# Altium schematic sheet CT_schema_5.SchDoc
size 283 x 147 mm
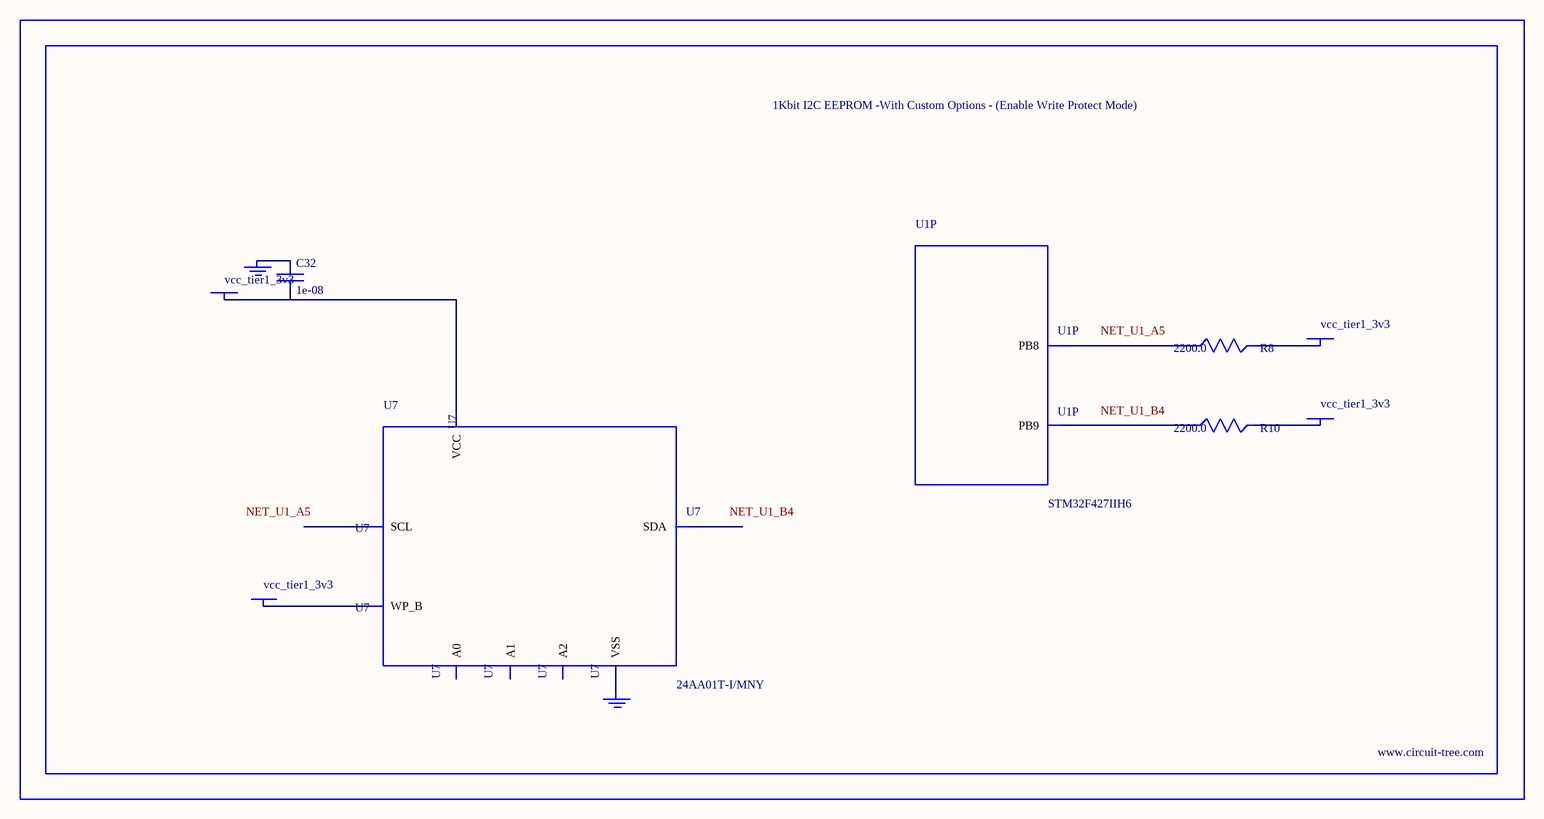
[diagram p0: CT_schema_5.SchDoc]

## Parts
BORDER4  (no value)
C32  1e-08  [C0402]
GND_INSTANCE_4_0  (no value)
GND_INSTANCE_4_1  (no value)
POWER_INSTANCE_4_0  vcc_tier1_3v3
POWER_INSTANCE_4_1  vcc_tier1_3v3
POWER_INSTANCE_4_2  vcc_tier1_3v3
POWER_INSTANCE_4_3  vcc_tier1_3v3
R8  2200.0  [R0603]
R10  2200.0  [R0603]
U1  STM32F427IIH6  [UFBGA176_25]  (part P of 17)
U7  24AA01T-I/MNY  [TDFN-8/6MM]

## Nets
NetC32_1: C32.1 GND_INSTANCE_4_0.0(GND)
NetC32_2: C32.2 POWER_INSTANCE_4_1.0(PWR) U7.8(VCC)
NetGND_INSTANCE_4_1_0: GND_INSTANCE_4_1.0(GND) U7.4(VSS)
NetPOWER_INSTANCE_4_0_0: POWER_INSTANCE_4_0.0(PWR) U7.7(WP_B)
NetPOWER_INSTANCE_4_2_0: POWER_INSTANCE_4_2.0(PWR) R8.2
NetPOWER_INSTANCE_4_3_0: POWER_INSTANCE_4_3.0(PWR) R10.2
NetR8_1: R8.1 U1.A5(PB8)
NetR10_1: R10.1 U1.B4(PB9)

Not connected (* = marked no-connect by the designer): U7 1(A0) 2(A1) 3(A2) 5(SDA) 6(SCL)

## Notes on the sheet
- Labels drawn without touching a wire or pin: NET_U1_A5, NET_U1_B4

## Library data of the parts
BORDER4 = BORDER_PAGE4
C32 = C0402C103K3RAC
GND_INSTANCE_4_0 GND_INSTANCE_4_1 = GND
POWER_INSTANCE_4_0-POWER_INSTANCE_4_3 = PWR
R8 R10 = RC0603JR-072K2L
